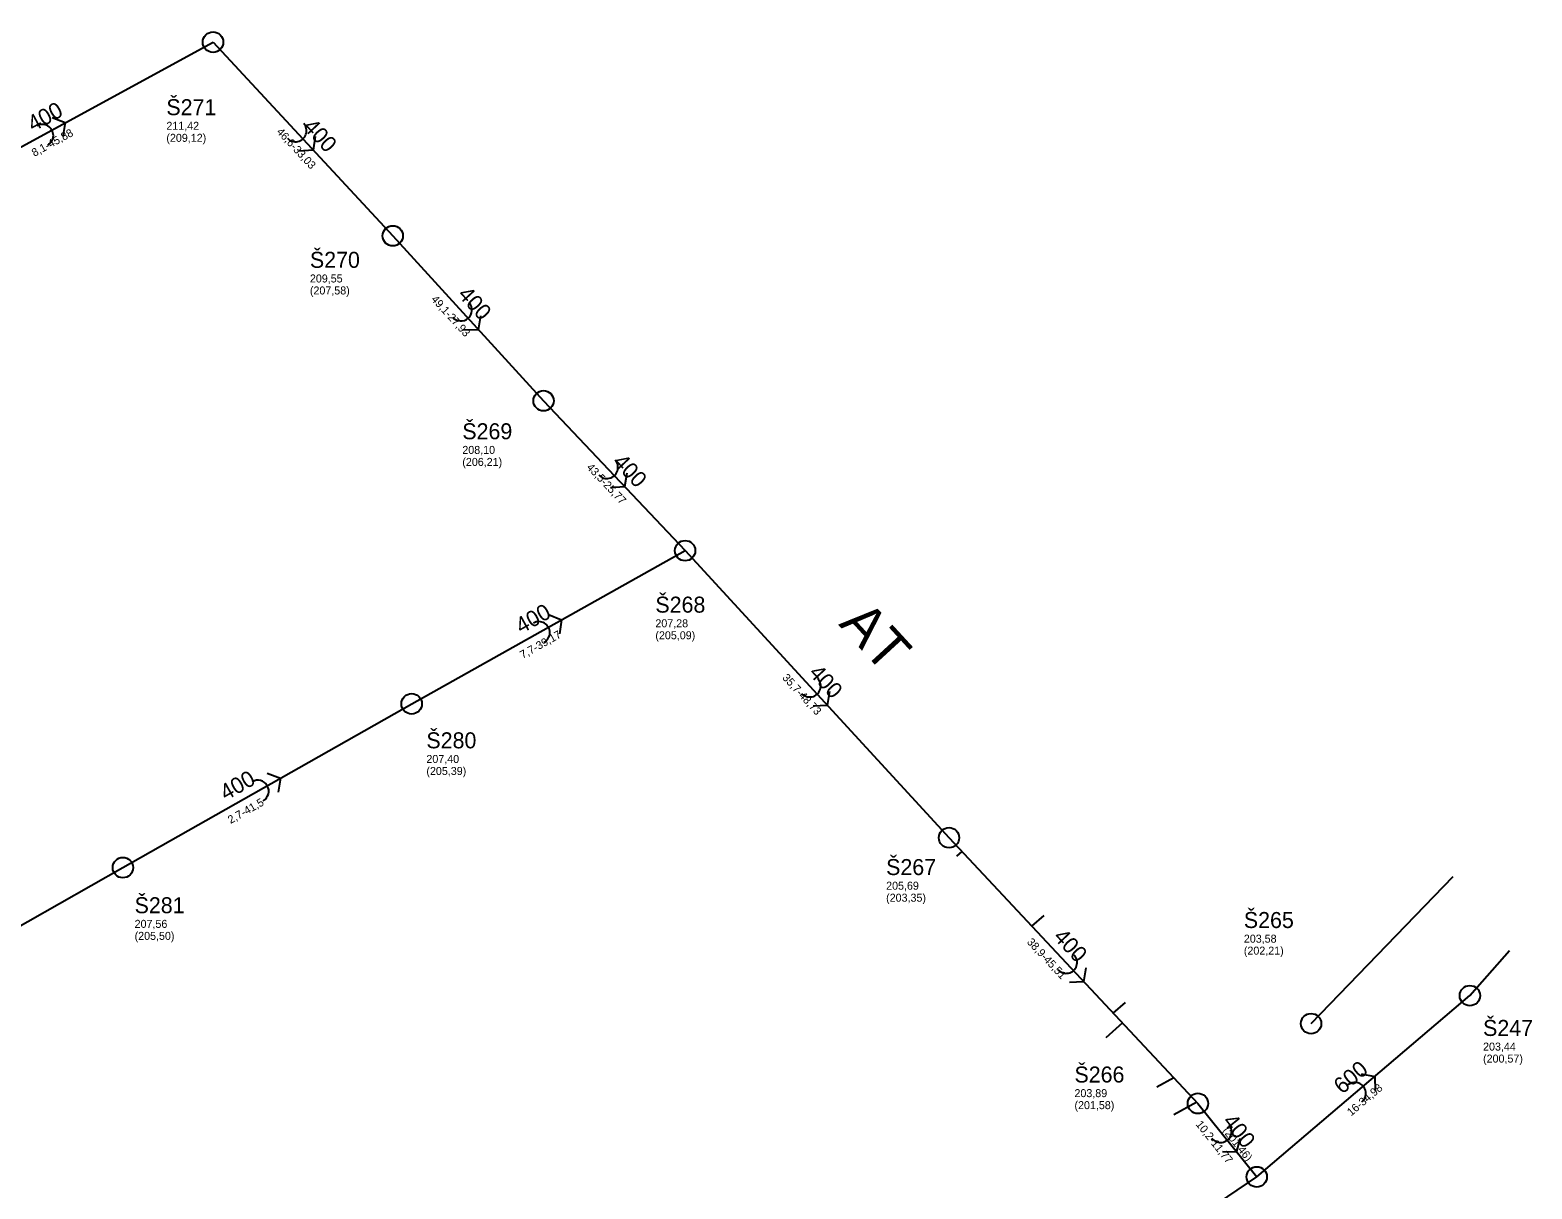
# Model space of a CAD drawing. Extents: x -574467 to -573663, y -1191209 to -1190406.
# Drawn here: x -573973 to -573785.3, y -1190695.6 to -1190550.7 of the extents above; entities that cross this region are included whole.
import ezdxf

# ---------------------------------------------------------------- set-up
doc = ezdxf.new("R2010")
doc.units = 0
for name, color, linetype in [('Vrstva 1', 7, 'Continuous'), ('Vrstva 12', 7, 'Continuous'), ('Vrstva 15', 7, 'Continuous'), ('Vrstva 29', 7, 'Continuous'), ('Vrstva 35', 7, 'Continuous'), ('Vrstva 41', 7, 'Continuous'), ('Vrstva 44', 7, 'Continuous'), ('Vrstva 45', 7, 'Continuous'), ('Vrstva 56', 7, 'Continuous'), ('Vrstva 57', 7, 'Continuous')]:
    doc.layers.add(name, color=color, linetype=linetype)

# ---------------------------------------------------------------- blocks, each defined once
blk = doc.blocks.new('100')
at = {"layer": 'Vrstva 1'}
blk.add_circle((0, 0), 1.27, dxfattribs=at)
blk = doc.blocks.new('86')
at = {"layer": 'Vrstva 1'}
blk.add_lwpolyline([(0.79, 1.37), (1.89, 0), (0.79, -1.38)], dxfattribs=at)
blk.add_arc((-1.37, 0), 1.37, 270, 90, dxfattribs=at)
blk = doc.blocks.new('91')
at = {"layer": 'Vrstva 1'}
blk.add_lwpolyline([(0.79, 1.37), (1.89, 0), (0.79, -1.38)], dxfattribs=at)
blk.add_arc((-1.37, 0), 1.37, 270, 90, dxfattribs=at)

msp = doc.modelspace()

# ---------------------------------------------------------------- linework, layer by layer
at = {"layer": 'Vrstva 12'}
for p, q in [((-573856.56, -1190653.38), (-573857.251, -1190653.953)), ((-573847.809, -1190662.721), (-573846.286, -1190661.38)), ((-573837.65, -1190673.566), (-573836.139, -1190672.264)), ((-573836.501, -1190674.792), (-573838.591, -1190676.661)), ((-573830.068, -1190681.66), (-573832.198, -1190682.819)), ((-573827.21, -1190684.71), (-573830.06, -1190686.292))]:
    msp.add_line(p, q, dxfattribs=at)
at = {"layer": 'Vrstva 15'}
for p, q in [((-573990.44, -1190574.19), (-573950.17, -1190552.21)), ((-573950.17, -1190552.21), (-573927.7, -1190576.42)), ((-573927.7, -1190576.42), (-573908.86, -1190597.04)), ((-573908.86, -1190597.04), (-573891.16, -1190615.77)), ((-573925.34, -1190634.91), (-573891.16, -1190615.77)), ((-573891.16, -1190615.77), (-573858.18, -1190651.65)), ((-573961.43, -1190655.39), (-573925.34, -1190634.91)), ((-573858.18, -1190651.65), (-573827.07, -1190684.86)), ((-573994.83, -1190674.34), (-573961.43, -1190655.39)), ((-573812.93, -1190674.89), (-573795.174, -1190656.491)), ((-573793.07, -1190671.39), (-573788.146, -1190665.734)), ((-573819.72, -1190694.05), (-573793.07, -1190671.39)), ((-573827.07, -1190684.86), (-573819.72, -1190694.05)), ((-573842.91, -1190709.71), (-573819.72, -1190694.05))]:
    msp.add_line(p, q, dxfattribs=at)

# ---------------------------------------------------------------- block references
at = {"layer": 'Vrstva 29'}
for p, xscale, yscale, rotation in [((-573950.17, -1190552.21), 1.00837761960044, 1.00837761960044, 168.3736213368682), ((-573927.7, -1190576.42), 0.9999999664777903, 0.9999999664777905, 132.99999806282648), ((-573908.86, -1190597.04), 0.9999999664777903, 0.9999999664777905, 132.99999806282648), ((-573891.16, -1190615.77), 0.9999999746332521, 0.9999999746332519, -99.99999944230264), ((-573925.34, -1190634.91), 1.0072562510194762, 1.0072562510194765, -151.23333635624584), ((-573858.18, -1190651.65), 0.9999999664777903, 0.9999999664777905, 132.99999806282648), ((-573961.43, -1190655.39), 1.0037041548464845, 1.0037041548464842, -150.62079141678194), ((-573793.07, -1190671.39), 0.9999999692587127, 0.9999999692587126, -136.00000080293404), ((-573812.93, -1190674.89), 0.999999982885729, 0.9999999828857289, -135), ((-573827.07, -1190684.86), 0.9999999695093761, 0.9999999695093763, 131.00000134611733), ((-573819.72, -1190694.05), 0.9999999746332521, 0.9999999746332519, -99.99999944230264)]:
    msp.add_blockref('100', p, dxfattribs=dict(at, xscale=xscale, yscale=yscale, rotation=rotation))
at = {"layer": 'Vrstva 41'}
for name, p, xscale, yscale, rotation in [('86', (-573970.305, -1190563.2), 1.0037041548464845, 1.0037041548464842, 29.379208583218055), ('86', (-573938.935, -1190564.315), 0.9999999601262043, 0.9999999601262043, -48.0000012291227), ('86', (-573918.28, -1190586.73), 0.9999999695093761, 0.9999999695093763, -48.99999865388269), ('86', (-573900.01, -1190606.405), 0.9999999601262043, 0.9999999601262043, -48.0000012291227), ('86', (-573908.25, -1190625.34), 1.0037041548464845, 1.0037041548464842, 29.379208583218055), ('86', (-573874.67, -1190633.71), 0.9999999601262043, 0.9999999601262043, -48.0000012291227), ('86', (-573943.385, -1190645.15), 0.9999999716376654, 0.9999999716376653, 29.999998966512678), ('86', (-573842.625, -1190668.255), 0.9999999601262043, 0.9999999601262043, -48.0000012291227), ('91', (-573806.395, -1190682.72), 0.9999999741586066, 0.9999999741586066, 39.999998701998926), ('86', (-573823.395, -1190689.455), 0.9999999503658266, 0.9999999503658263, -52.00000018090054)]:
    msp.add_blockref(name, p, dxfattribs=dict(at, xscale=xscale, yscale=yscale, rotation=rotation))

# ---------------------------------------------------------------- texts
at = {"layer": 'Vrstva 35'}
msp.add_text('AT', height=5, rotation=312.59, dxfattribs=at).set_placement((-573872.059, -1190625.012))
at = {"layer": 'Vrstva 44'}
for s, rotation, p in [('400', 28.63, (-573972.661, -1190563.459)), ('400', 312.87, (-573939.02, -1190562.896)), ('400', 312.42, (-573919.688, -1190583.85)), ('400', 313.38, (-573900.279, -1190604.815)), ('400', 29.25, (-573911.649, -1190626.211)), ('400', 312.59, (-573875.799, -1190631.147)), ('400', 29.57, (-573948.577, -1190647.064)), ('400', 313.13, (-573845.243, -1190664.15)), ('600', 40.37, (-573809.035, -1190683.787)), ('400', 308.65, (-573824.082, -1190687.156))]:
    msp.add_text(s, height=2, rotation=rotation, dxfattribs=at).set_placement(p)
at = {"layer": 'Vrstva 45'}
for s, rotation, p in [('8,1-45,88', 28.63, (-573972.499, -1190566.56)), ('46,6-33,03', 312.87, (-573942.297, -1190563.485)), ('49,1-27,93', 312.42, (-573922.973, -1190584.411)), ('43,5-25,77', 313.38, (-573903.548, -1190605.426)), ('7,7-39,17', 29.25, (-573911.465, -1190629.316)), ('35,7-48,73', 312.59, (-573879.085, -1190631.715)), ('2,7-41,5', 29.57, (-573947.97, -1190649.94)), ('38,9-45,51', 313.13, (-573848.512, -1190664.75)), ('16-34,98', 40.37, (-573807.914, -1190686.499)), ('10,2-11,77', 308.65, (-573827.396, -1190687.5)), ('(201,46)', 308.65, (-573824.06, -1190688.302))]:
    msp.add_text(s, height=1, rotation=rotation, dxfattribs=at).set_placement(p)
at = {"layer": 'Vrstva 56'}
for s, p in [('211,42 ', (-573956, -1190563.17)), ('(209,12)', (-573956, -1190564.67)), ('209,55 ', (-573938.06, -1190582.25)), ('(207,58)', (-573938.06, -1190583.75)), ('208,10 ', (-573919.01, -1190603.68)), ('(206,21)', (-573919.01, -1190605.18)), ('207,28 ', (-573894.88, -1190625.35)), ('(205,09)', (-573894.88, -1190626.85)), ('207,40 ', (-573923.5, -1190642.31)), ('(205,39)', (-573923.5, -1190643.81)), ('205,69 ', (-573866.04, -1190658.15)), ('(203,35)', (-573866.04, -1190659.65)), ('207,56 ', (-573959.97, -1190662.92)), ('(205,50)', (-573959.97, -1190664.42)), ('203,58 ', (-573821.33, -1190664.77)), ('(202,21)', (-573821.33, -1190666.27)), ('203,44 ', (-573791.43, -1190678.26)), ('(200,57)', (-573791.43, -1190679.76)), ('203,89 ', (-573842.5, -1190684.08)), ('(201,58)', (-573842.5, -1190685.58))]:
    msp.add_text(s, height=1, dxfattribs=at).set_placement(p)
at = {"layer": 'Vrstva 57'}
for s, p in [('Š271', (-573956, -1190561.34)), ('Š270', (-573938.06, -1190580.42)), ('Š269', (-573919.01, -1190601.85)), ('Š268', (-573894.88, -1190623.52)), ('Š280', (-573923.5, -1190640.48)), ('Š267', (-573866.04, -1190656.32)), ('Š281', (-573959.97, -1190661.09)), ('Š265', (-573821.33, -1190662.94)), ('Š247', (-573791.43, -1190676.43)), ('Š266', (-573842.5, -1190682.25))]:
    msp.add_text(s, height=2, dxfattribs=at).set_placement(p)

doc.saveas('drawing.dxf')
